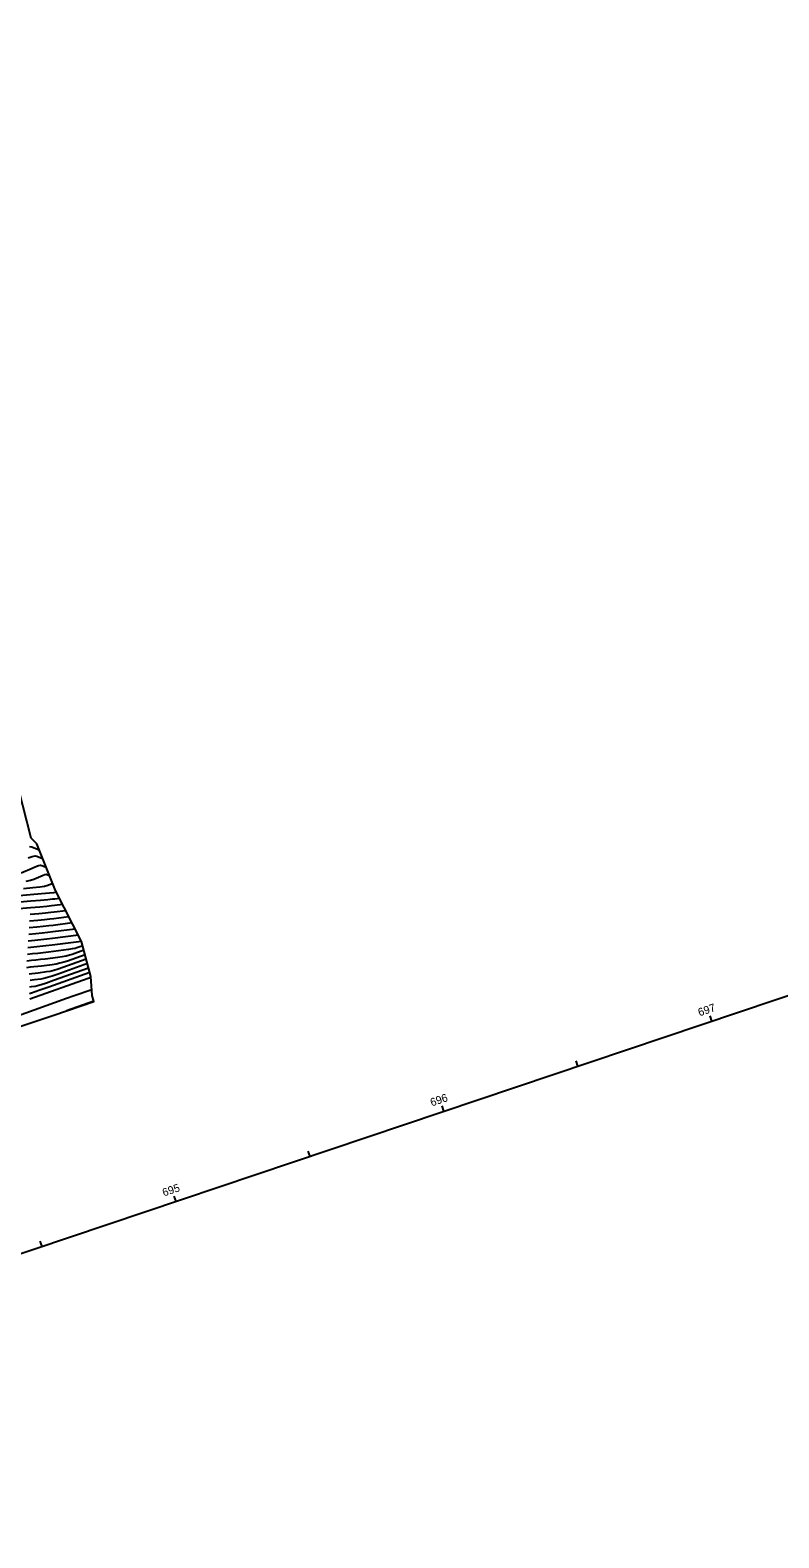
# Model space of a CAD drawing. Extents: x 2175772 to 2185556, y 721391 to 722853.
# Drawn here: x 2179161 to 2179426, y 721745 to 722278 of the extents above; entities that cross this region are included whole.
import ezdxf

# ---------------------------------------------------------------- set-up
doc = ezdxf.new("R2010")
doc.units = 0
for name, color, linetype in [('DT_X_Contour_Major', 7, 'Continuous'), ('DT_X_Contour_Minor', 7, 'Continuous'), ('DT_X_TIN_Hull', 7, 'Continuous'), ('GE_X_CL_20', 7, 'Continuous')]:
    doc.layers.add(name, color=color, linetype=linetype)

msp = doc.modelspace()

# ---------------------------------------------------------------- linework, layer by layer
at = {"layer": 'DT_X_Contour_Major'}
for points in [[(2179169.16, 721975.98), (2179168.79, 721976.14), (2179168.67, 721976.15), (2179168.49, 721976.11), (2179168.23, 721976.03), (2179167.9, 721975.89), (2179166.94, 721975.47), (2179166.15, 721975.29), (2179164.51, 721975.06), (2179162.02, 721974.8), (2179158.68, 721974.49)], [(2179174.79, 721964.53), (2179169.39, 721963.84), (2179167.99, 721963.67), (2179166.1, 721963.48), (2179163.73, 721963.25), (2179160.87, 721962.99)], [(2179179.66, 721954.28), (2179177.6, 721953.54), (2179176.97, 721953.37), (2179175.96, 721953.18), (2179174.57, 721952.96), (2179172.81, 721952.72), (2179167.6, 721952.06), (2179165.67, 721951.82), (2179163.77, 721951.6), (2179161.92, 721951.41), (2179160.09, 721951.24)], [(2179181.74, 721946.42), (2179169.29, 721941.95), (2179166.88, 721941.11), (2179165.01, 721940.48), (2179163.67, 721940.08), (2179162.86, 721939.9), (2179161.41, 721939.71), (2179160.87, 721939.64)]]:
    msp.add_lwpolyline(points, dxfattribs=at)
at = {"layer": 'DT_X_Contour_Minor'}
for points in [[(2179160.86, 721989.44), (2179161.66, 721989.36), (2179164.22, 721988.23)], [(2179160.41, 721985.44), (2179161.81, 721985.91), (2179162.82, 721986.12), (2179163.44, 721986.06), (2179165.45, 721985.17)], [(2179157.89, 721980.1), (2179161.72, 721981.77), (2179163.02, 721982.3), (2179164.03, 721982.65), (2179164.77, 721982.79), (2179165.22, 721982.75), (2179166.69, 721982.11)], [(2179167.92, 721979.04), (2179167.01, 721979.45), (2179166.72, 721979.47), (2179166.26, 721979.38), (2179165.62, 721979.17), (2179164.81, 721978.83), (2179162.41, 721977.78), (2179161.24, 721977.4), (2179159.52, 721977.06)], [(2179170.35, 721973.2), (2179169.95, 721973.15), (2179169.36, 721973.09), (2179165.13, 721972.72), (2179150.45, 721971.42)], [(2179171.46, 721971.03), (2179169.81, 721970.82), (2179169.02, 721970.74), (2179167.34, 721970.58), (2179164.78, 721970.35), (2179161.34, 721970.05), (2179150.99, 721969.13)], [(2179172.57, 721968.86), (2179169.67, 721968.49), (2179168.67, 721968.38), (2179166.93, 721968.21), (2179164.43, 721967.98), (2179161.18, 721967.7), (2179151.52, 721966.84)], [(2179175.9, 721962.36), (2179169.25, 721961.51), (2179167.65, 721961.32), (2179165.69, 721961.11), (2179163.38, 721960.88), (2179160.72, 721960.64)], [(2179173.68, 721966.7), (2179169.53, 721966.17), (2179168.33, 721966.03), (2179166.52, 721965.85), (2179164.08, 721965.62), (2179161.03, 721965.34)], [(2179178.12, 721958.02), (2179168.97, 721956.85), (2179166.97, 721956.61), (2179164.87, 721956.37), (2179162.68, 721956.15), (2179160.4, 721955.94)], [(2179177.01, 721960.19), (2179169.11, 721959.18), (2179167.31, 721958.96), (2179165.28, 721958.74), (2179163.03, 721958.52), (2179160.56, 721958.29)], [(2179180.07, 721952.71), (2179175.94, 721951.22), (2179174.95, 721950.92), (2179173.77, 721950.64), (2179172.39, 721950.38), (2179170.82, 721950.16), (2179166.37, 721949.59), (2179164.71, 721949.38), (2179163.09, 721949.2), (2179161.5, 721949.03), (2179159.94, 721948.89)], [(2179179.23, 721955.85), (2179168.83, 721954.52), (2179166.62, 721954.25), (2179164.46, 721954), (2179162.33, 721953.78), (2179160.25, 721953.59)], [(2179180.49, 721951.14), (2179174.27, 721948.9), (2179172.93, 721948.46), (2179171.58, 721948.1), (2179170.21, 721947.81), (2179168.83, 721947.59), (2179165.13, 721947.12), (2179163.75, 721946.95), (2179162.4, 721946.8), (2179161.08, 721946.66), (2179159.78, 721946.54)], [(2179180.9, 721949.56), (2179172.61, 721946.59), (2179170.92, 721946.01), (2179169.39, 721945.56), (2179168.03, 721945.23), (2179166.84, 721945.03), (2179163.89, 721944.65), (2179162.79, 721944.51), (2179161.71, 721944.39), (2179160.66, 721944.28)], [(2179181.32, 721947.99), (2179170.95, 721944.27), (2179168.9, 721943.56), (2179167.2, 721943.02), (2179165.85, 721942.65), (2179164.85, 721942.46), (2179162.65, 721942.18), (2179161.83, 721942.08), (2179161.03, 721941.99)], [(2179182.15, 721944.85), (2179167.62, 721939.64), (2179164.87, 721938.65), (2179162.82, 721937.94), (2179161.49, 721937.5), (2179160.87, 721937.33)], [(2179182.56, 721943.03), (2179181.62, 721942.7), (2179160.99, 721935.35)], [(2179182.85, 721938.75), (2179176.64, 721936.57), (2179173.88, 721935.59), (2179162.51, 721931.54), (2179150.17, 721927.16)], [(2179183.58, 721934.68), (2179173.98, 721931.27)]]:
    msp.add_lwpolyline(points, dxfattribs=at)
at = {"layer": 'DT_X_TIN_Hull'}
msp.add_lwpolyline([(2179145.75, 721921.77), (2179169.44, 721929.75), (2179183.63, 721934.52), (2179182.99, 721936.63), (2179182.53, 721943.43), (2179179.24, 721955.83), (2179170, 721973.9), (2179163.38, 721990.32), (2179161.43, 721992.4), (2179152.44, 722027.56)], dxfattribs=at)
at = {"layer": 'GE_X_CL_20'}
for p, q in [((2178697.33, 721690.31), (2180444.45, 722278.43)), ((2179402.23, 721927.59), (2179401.59, 721929.49)), ((2179354.84, 721911.64), (2179354.2, 721913.54)), ((2179307.45, 721895.69), (2179306.81, 721897.59)), ((2179260.07, 721879.74), (2179259.43, 721881.63)), ((2179212.68, 721863.79), (2179212.04, 721865.68)), ((2179165.29, 721847.84), (2179164.65, 721849.73))]:
    msp.add_line(p, q, dxfattribs=at)

# ---------------------------------------------------------------- texts
for s, p in [('697', (2179397.85, 721929.29)), ('696', (2179303.13, 721897.4)), ('695', (2179208.37, 721865.5))]:
    msp.add_text(s, height=2.8, rotation=18.6042, dxfattribs=at).set_placement(p)

doc.saveas('drawing.dxf')
